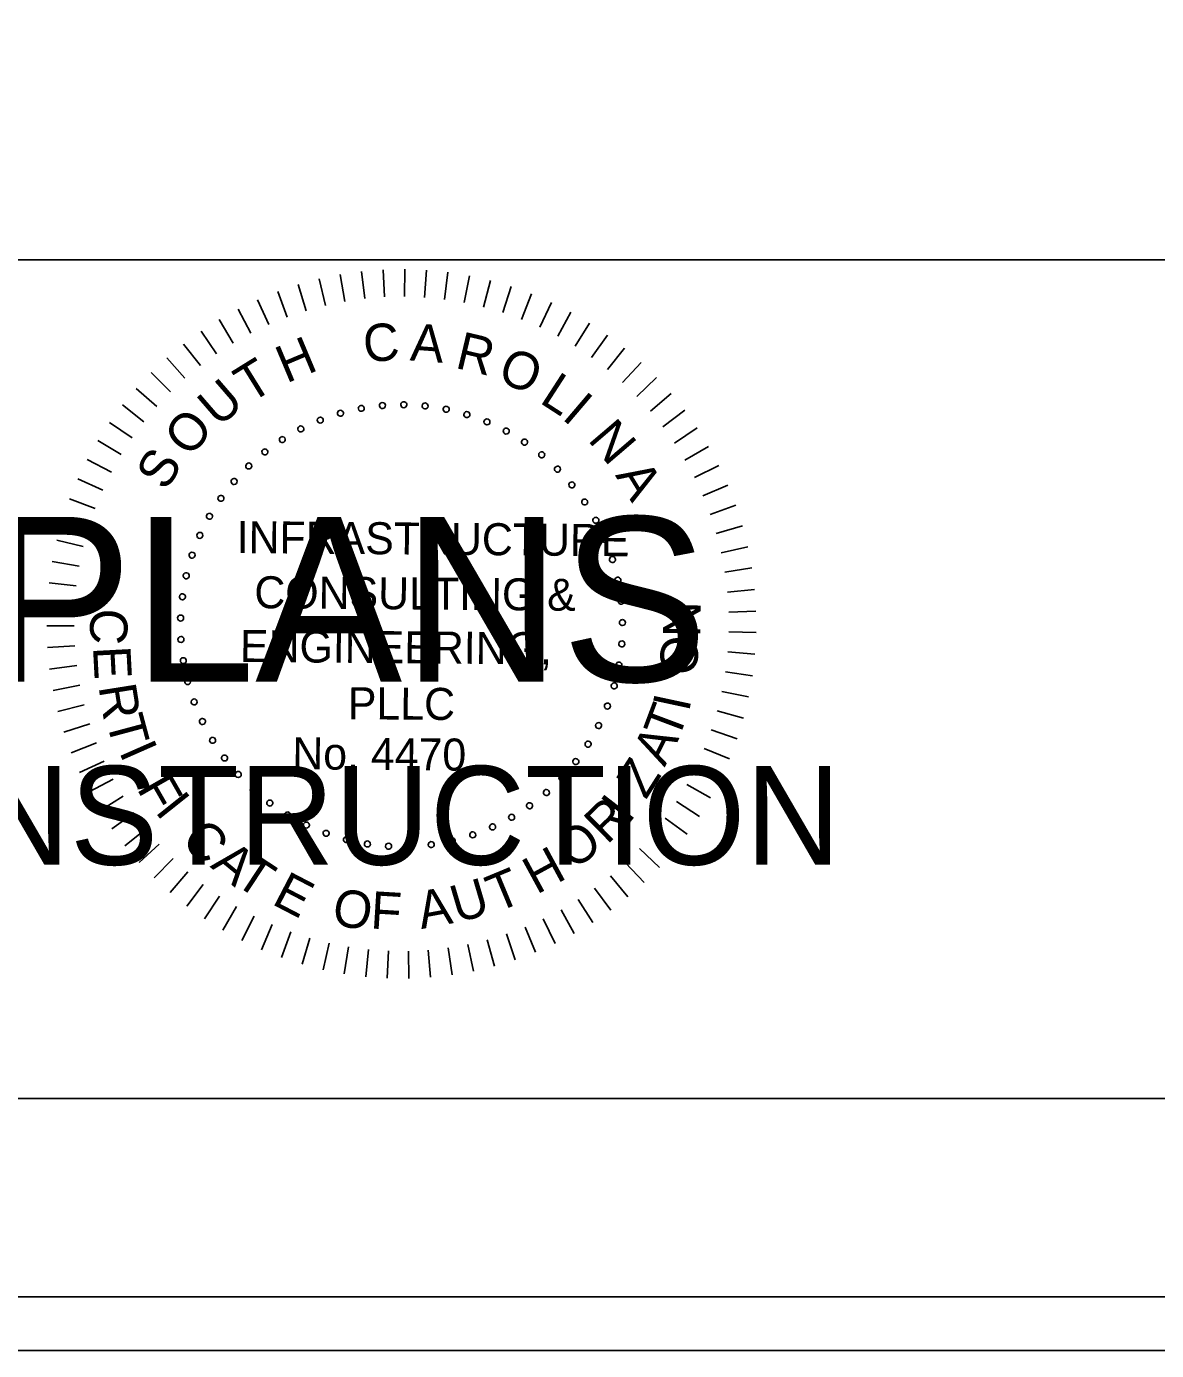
# Model space of a CAD drawing. Extents: x 967 to 1326, y 964 to 2864.
# Drawn here: x 1189.3 to 1212.88, y 2363.72 to 2391.36 of the extents above; entities that cross this region are included whole.
import ezdxf

# ---------------------------------------------------------------- set-up
doc = ezdxf.new("R2010")
doc.units = 0
for name, color, linetype in [('RD_PD_Final_TX', 7, 'Continuous'), ('RD_XS_TX_Elev_PR', 7, 'Continuous'), ('RD_XS_TX_Misc', 7, 'Continuous'), ('RD_XS_TX_ShdSlope', 7, 'Continuous')]:
    doc.layers.add(name, color=color, linetype=linetype)

msp = doc.modelspace()

# ---------------------------------------------------------------- linework, layer by layer
at = {"layer": 'RD_PD_Final_TX'}
for p, q in [((996.114, 2386.486), (1323.886, 2386.486)), ((1323.886, 2368.983), (996.114, 2368.983))]:
    msp.add_line(p, q, dxfattribs=at)
at = {"layer": 'RD_XS_TX_Elev_PR'}
for points in [[(967.409, 2363.72), (1326.285, 2363.72), (1326.285, 2583.72), (967.409, 2583.72)], [(988.525, 2364.84), (1326.285, 2364.84), (1326.285, 2582.6), (988.525, 2582.6)]]:
    msp.add_lwpolyline(points, close=True, dxfattribs=at)
at = {"layer": 'RD_XS_TX_ShdSlope'}
for p, q in [((1195.846, 2386.181), (1195.945, 2385.62)), ((1196.292, 2386.245), (1196.357, 2385.68)), ((1196.742, 2386.282), (1196.772, 2385.714)), ((1197.194, 2386.292), (1197.189, 2385.723)), ((1197.645, 2386.274), (1197.606, 2385.706)), ((1198.094, 2386.228), (1198.02, 2385.664)), ((1198.54, 2386.156), (1198.432, 2385.596)), ((1194.968, 2385.971), (1195.134, 2385.427)), ((1195.403, 2386.09), (1195.536, 2385.536)), ((1198.98, 2386.056), (1198.838, 2385.504)), ((1199.414, 2385.929), (1199.238, 2385.387)), ((1194.122, 2385.656), (1194.353, 2385.136)), ((1194.54, 2385.827), (1194.739, 2385.293)), ((1199.839, 2385.777), (1199.63, 2385.246)), ((1200.253, 2385.598), (1200.013, 2385.082)), ((1193.715, 2385.461), (1193.978, 2384.956)), ((1200.656, 2385.395), (1200.385, 2384.894)), ((1193.321, 2385.241), (1193.614, 2384.752)), ((1201.047, 2385.167), (1200.745, 2384.684)), ((1192.94, 2384.997), (1193.263, 2384.528)), ((1201.422, 2384.917), (1201.092, 2384.453)), ((1192.576, 2384.731), (1192.926, 2384.282)), ((1201.781, 2384.643), (1201.424, 2384.2)), ((1192.228, 2384.443), (1192.605, 2384.016)), ((1202.124, 2384.349), (1201.739, 2383.928)), ((1191.899, 2384.134), (1192.301, 2383.731)), ((1202.447, 2384.034), (1202.038, 2383.638)), ((1191.589, 2383.805), (1192.015, 2383.428)), ((1202.751, 2383.7), (1202.318, 2383.329)), ((1191.299, 2383.459), (1191.748, 2383.108)), ((1203.034, 2383.348), (1202.579, 2383.004)), ((1191.032, 2383.095), (1191.501, 2382.772)), ((1203.294, 2382.979), (1202.82, 2382.664)), ((1190.787, 2382.716), (1191.274, 2382.422)), ((1203.532, 2382.595), (1203.04, 2382.31)), ((1190.565, 2382.323), (1191.07, 2382.059)), ((1203.746, 2382.198), (1203.237, 2381.943)), ((1190.368, 2381.916), (1190.888, 2381.684)), ((1203.936, 2381.788), (1203.412, 2381.564)), ((1190.196, 2381.499), (1190.729, 2381.299)), ((1204.1, 2381.367), (1203.563, 2381.176)), ((1190.05, 2381.072), (1190.594, 2380.905)), ((1204.238, 2380.937), (1203.691, 2380.779)), ((1189.93, 2380.636), (1190.484, 2380.503)), ((1204.349, 2380.5), (1203.794, 2380.375)), ((1189.837, 2380.195), (1190.398, 2380.095)), ((1204.434, 2380.056), (1203.872, 2379.966)), ((1189.771, 2379.748), (1190.337, 2379.683)), ((1204.491, 2379.608), (1203.925, 2379.552)), ((1189.732, 2379.298), (1190.301, 2379.267)), ((1204.522, 2379.158), (1203.953, 2379.137)), ((1189.721, 2378.847), (1190.29, 2378.851)), ((1204.524, 2378.706), (1203.955, 2378.72)), ((1189.737, 2378.396), (1190.306, 2378.434)), ((1204.499, 2378.256), (1203.932, 2378.304)), ((1189.781, 2377.946), (1190.346, 2378.019)), ((1204.447, 2377.807), (1203.884, 2377.89)), ((1189.852, 2377.5), (1190.412, 2377.608)), ((1204.367, 2377.363), (1203.81, 2377.479)), ((1189.951, 2377.06), (1190.502, 2377.201)), ((1204.261, 2376.924), (1203.712, 2377.074)), ((1190.076, 2376.626), (1190.617, 2376.8)), ((1204.128, 2376.492), (1203.589, 2376.676)), ((1190.227, 2376.2), (1190.757, 2376.408)), ((1203.969, 2376.07), (1203.442, 2376.286)), ((1190.403, 2375.785), (1190.92, 2376.024)), ((1190.605, 2375.381), (1191.106, 2375.651)), ((1203.784, 2375.658), (1203.271, 2375.906)), ((1203.574, 2375.258), (1203.078, 2375.537)), ((1190.831, 2374.99), (1191.315, 2375.291)), ((1203.341, 2374.871), (1202.862, 2375.18)), ((1191.081, 2374.614), (1191.545, 2374.943)), ((1203.085, 2374.5), (1202.626, 2374.837)), ((1191.353, 2374.253), (1191.796, 2374.61)), ((1191.646, 2373.91), (1192.067, 2374.293)), ((1202.806, 2374.145), (1202.368, 2374.509)), ((1191.96, 2373.585), (1192.356, 2373.994)), ((1202.506, 2373.807), (1202.092, 2374.197)), ((1192.293, 2373.28), (1192.664, 2373.712)), ((1202.186, 2373.488), (1201.796, 2373.903)), ((1192.644, 2372.996), (1192.988, 2373.45)), ((1201.847, 2373.19), (1201.484, 2373.628)), ((1193.011, 2372.734), (1193.327, 2373.208)), ((1201.491, 2372.912), (1201.155, 2373.372)), ((1193.394, 2372.495), (1193.68, 2372.987)), ((1200.731, 2372.425), (1200.453, 2372.922)), ((1201.119, 2372.657), (1200.811, 2373.136)), ((1193.791, 2372.279), (1194.047, 2372.788)), ((1194.2, 2372.088), (1194.424, 2372.612)), ((1200.331, 2372.217), (1200.083, 2372.73)), ((1194.62, 2371.923), (1194.812, 2372.459)), ((1195.05, 2371.783), (1195.208, 2372.33)), ((1199.495, 2371.877), (1199.312, 2372.416)), ((1199.918, 2372.034), (1199.702, 2372.561)), ((1195.487, 2371.67), (1195.612, 2372.225)), ((1195.93, 2371.584), (1196.021, 2372.146)), ((1196.377, 2371.524), (1196.434, 2372.091)), ((1196.828, 2371.493), (1196.85, 2372.062)), ((1197.279, 2371.488), (1197.267, 2372.058)), ((1197.73, 2371.512), (1197.683, 2372.079)), ((1198.179, 2371.562), (1198.097, 2372.126)), ((1198.624, 2371.64), (1198.508, 2372.198)), ((1199.063, 2371.745), (1198.913, 2372.295))]:
    msp.add_line(p, q, dxfattribs=at)
for centre, start, end in [((1196.285, 2383.388), 10.6038, 190.6038), ((1196.285, 2383.388), 190.6038, 10.6038), ((1196.727, 2383.447), 5.0653, 185.0653), ((1196.727, 2383.447), 185.0653, 5.0653), ((1197.172, 2383.464), 359.5268, 179.5268), ((1197.172, 2383.464), 179.5268, 359.5268), ((1197.617, 2383.438), 173.9884, 353.9884), ((1197.617, 2383.438), 353.9884, 173.9884), ((1198.057, 2383.369), 168.4499, 348.4499), ((1198.057, 2383.369), 348.4499, 168.4499), ((1195.429, 2383.142), 21.6807, 201.6807), ((1195.429, 2383.142), 201.6807, 21.6807), ((1195.851, 2383.285), 16.1422, 196.1422), ((1195.851, 2383.285), 196.1422, 16.1422), ((1198.489, 2383.258), 162.9114, 342.9114), ((1198.489, 2383.258), 342.9114, 162.9114), ((1198.908, 2383.106), 157.373, 337.373), ((1198.908, 2383.106), 337.373, 157.373), ((1195.023, 2382.958), 27.2191, 207.2191), ((1195.023, 2382.958), 207.2191, 27.2191), ((1199.31, 2382.914), 151.8345, 331.8345), ((1199.31, 2382.914), 331.8345, 151.8345), ((1194.637, 2382.736), 32.7576, 212.7576), ((1194.637, 2382.736), 212.7576, 32.7576), ((1199.692, 2382.684), 146.2961, 326.2961), ((1199.692, 2382.684), 326.2961, 146.2961), ((1194.274, 2382.478), 38.2961, 218.2961), ((1194.274, 2382.478), 218.2961, 38.2961), ((1200.05, 2382.419), 140.7576, 320.7576), ((1200.05, 2382.419), 320.7576, 140.7576), ((1193.937, 2382.186), 43.8345, 223.8345), ((1193.937, 2382.186), 223.8345, 43.8345), ((1200.38, 2382.12), 135.2191, 315.2191), ((1200.38, 2382.12), 315.2191, 135.2191), ((1193.63, 2381.862), 49.373, 229.373), ((1193.63, 2381.862), 229.373, 49.373), ((1200.68, 2381.79), 129.6807, 309.6807), ((1200.68, 2381.79), 309.6807, 129.6807), ((1193.356, 2381.511), 54.9114, 234.9114), ((1193.356, 2381.511), 234.9114, 54.9114), ((1200.947, 2381.433), 124.1422, 304.1422), ((1200.947, 2381.433), 304.1422, 124.1422), ((1193.117, 2381.135), 60.4499, 240.4499), ((1193.117, 2381.135), 240.4499, 60.4499), ((1201.179, 2381.052), 118.6038, 298.6038), ((1201.179, 2381.052), 298.6038, 118.6038), ((1192.915, 2380.737), 65.9884, 245.9884), ((1192.915, 2380.737), 245.9884, 65.9884), ((1201.372, 2380.651), 113.0653, 293.0653), ((1201.372, 2380.651), 293.0653, 113.0653), ((1192.753, 2380.322), 71.5268, 251.5268), ((1192.753, 2380.322), 251.5268, 71.5268), ((1201.526, 2380.233), 107.5268, 287.5268), ((1201.526, 2380.233), 287.5268, 107.5268), ((1192.632, 2379.894), 77.0653, 257.0653), ((1192.632, 2379.894), 257.0653, 77.0653), ((1201.638, 2379.801), 101.9884, 281.9884), ((1201.638, 2379.801), 281.9884, 101.9884), ((1192.552, 2379.455), 82.6038, 262.6038), ((1192.552, 2379.455), 262.6038, 82.6038), ((1201.709, 2379.361), 96.4499, 276.4499), ((1201.709, 2379.361), 276.4499, 96.4499), ((1192.515, 2379.011), 88.1422, 268.1422), ((1192.515, 2379.011), 268.1422, 88.1422), ((1201.737, 2378.917), 90.9114, 270.9114), ((1201.737, 2378.917), 270.9114, 90.9114), ((1192.522, 2378.565), 93.6807, 273.6807), ((1192.522, 2378.565), 273.6807, 93.6807), ((1201.721, 2378.471), 85.373, 265.373), ((1201.721, 2378.471), 265.373, 85.373), ((1192.571, 2378.122), 99.2191, 279.2191), ((1192.571, 2378.122), 279.2191, 99.2191), ((1201.663, 2378.029), 79.8345, 259.8345), ((1201.663, 2378.029), 259.8345, 79.8345), ((1192.662, 2377.686), 104.7576, 284.7576), ((1192.662, 2377.686), 284.7576, 104.7576), ((1201.563, 2377.595), 74.2961, 254.2961), ((1201.563, 2377.595), 254.2961, 74.2961), ((1192.796, 2377.261), 110.2961, 290.2961), ((1192.796, 2377.261), 290.2961, 110.2961), ((1201.42, 2377.173), 68.7576, 248.7576), ((1201.42, 2377.173), 248.7576, 68.7576), ((1192.97, 2376.851), 115.8345, 295.8345), ((1192.97, 2376.851), 295.8345, 115.8345), ((1201.238, 2376.766), 63.2191, 243.2191), ((1201.238, 2376.766), 243.2191, 63.2191), ((1193.182, 2376.459), 121.373, 301.373), ((1193.182, 2376.459), 301.373, 121.373), ((1201.018, 2376.379), 57.6807, 237.6807), ((1201.018, 2376.379), 237.6807, 57.6807), ((1193.432, 2376.09), 126.9114, 306.9114), ((1193.432, 2376.09), 306.9114, 126.9114), ((1200.761, 2376.014), 52.1422, 232.1422), ((1200.761, 2376.014), 232.1422, 52.1422), ((1193.715, 2375.746), 132.4499, 312.4499), ((1193.715, 2375.746), 312.4499, 132.4499), ((1200.47, 2375.677), 46.6038, 226.6038), ((1200.47, 2375.677), 226.6038, 46.6038), ((1194.031, 2375.431), 137.9884, 317.9884), ((1194.031, 2375.431), 317.9884, 137.9884), ((1200.148, 2375.369), 41.0653, 221.0653), ((1200.148, 2375.369), 221.0653, 41.0653), ((1194.376, 2375.149), 143.5268, 323.5268), ((1194.376, 2375.149), 323.5268, 143.5268), ((1199.798, 2375.093), 35.5268, 215.5268), ((1199.798, 2375.093), 215.5268, 35.5268), ((1194.746, 2374.901), 149.0653, 329.0653), ((1194.746, 2374.901), 329.0653, 149.0653), ((1199.422, 2374.853), 29.9884, 209.9884), ((1199.422, 2374.853), 209.9884, 29.9884), ((1195.139, 2374.69), 154.6038, 334.6038), ((1195.139, 2374.69), 334.6038, 154.6038), ((1195.55, 2374.517), 160.1422, 340.1422), ((1195.55, 2374.517), 340.1422, 160.1422), ((1198.611, 2374.486), 18.9114, 198.9114), ((1199.026, 2374.65), 24.4499, 204.4499), ((1199.026, 2374.65), 204.4499, 24.4499), ((1195.975, 2374.386), 165.6807, 345.6807), ((1195.975, 2374.386), 345.6807, 165.6807), ((1196.412, 2374.295), 171.2191, 351.2191), ((1196.412, 2374.295), 351.2191, 171.2191), ((1196.855, 2374.248), 356.7576, 176.7576), ((1197.301, 2374.243), 2.2961, 182.2961), ((1197.745, 2374.282), 7.8345, 187.8345), ((1197.745, 2374.282), 187.8345, 7.8345), ((1198.183, 2374.363), 13.373, 193.373), ((1198.183, 2374.363), 193.373, 13.373), ((1198.611, 2374.486), 198.9114, 18.9114), ((1196.855, 2374.248), 176.7576, 356.7576), ((1197.301, 2374.243), 182.2961, 2.2961)]:
    msp.add_arc(centre, 0.0627, start, end, dxfattribs=at)

# ---------------------------------------------------------------- texts
at = {"layer": 'RD_XS_TX_Misc'}
for s, height, p in [('FINAL PLANS', 3.4375, (1174.145, 2377.685)), ('NOT FOR CONSTRUCTION', 2.0625, (1170.901, 2373.86))]:
    msp.add_text(s, height=height, dxfattribs=at).set_placement(p)
at = {"layer": 'RD_XS_TX_ShdSlope'}
for s, height, rotation, p in [('C', 0.78, 4.7281, (1196.355, 2384.346)), ('A', 0.78, 355.6981, (1197.29, 2384.39)), ('H', 0.78, 22.7882, (1194.72, 2383.904)), ('R', 0.78, 346.6681, (1198.222, 2384.238)), ('O', 0.78, 337.638, (1199.096, 2383.972)), ('T', 0.78, 31.8182, (1193.961, 2383.478)), ('U', 0.78, 40.8482, (1193.306, 2382.976)), ('L', 0.78, 327.108, (1199.981, 2383.52)), ('I', 0.78, 319.578, (1200.451, 2383.182)), ('O', 0.78, 49.8782, (1192.707, 2382.341)), ('N', 0.78, 310.548, (1200.994, 2382.728)), ('S', 0.78, 58.9083, (1192.211, 2381.642)), ('A', 0.78, 301.5179, (1201.576, 2381.991)), ('INFRASTRUCTURE', 0.66873, 359.5268, (1193.682, 2380.367)), ('CONSULTING &', 0.66873, 359.5268, (1194.051, 2379.217)), ('N', 0.78, 89.2085, (1203.359, 2378.604)), ('C', 0.78, 267.025, (1190.646, 2379.227)), ('ENGINEERING,', 0.66873, 359.5268, (1193.751, 2378.095)), ('O', 0.78, 83.2085, (1203.26, 2377.786)), ('E', 0.78, 273.025, (1190.685, 2378.408)), ('R', 0.78, 279.025, (1190.799, 2377.583)), ('PLLC', 0.6687, 359.5268, (1196.002, 2376.9)), ('I', 0.78, 77.9093, (1203.121, 2377.032)), ('T', 0.78, 285.025, (1190.955, 2376.878)), ('T', 0.78, 69.3954, (1202.891, 2376.428)), ('No. 4470', 0.6687, 359.5268, (1194.843, 2375.855)), ('A', 0.78, 63.3954, (1202.616, 2375.888)), ('I', 0.78, 293.7713, (1191.221, 2376.225)), ('Z', 0.78, 57.3954, (1202.224, 2375.206)), ('F', 0.78, 299.7713, (1191.589, 2375.455)), ('I', 0.78, 308.5268, (1191.965, 2374.973)), ('R', 0.78, 44.5268, (1201.415, 2374.267)), ('I', 0.78, 52.3339, (1201.856, 2374.69)), ('C', 0.78, 314.5268, (1192.496, 2374.346)), ('O', 0.78, 38.5268, (1200.73, 2373.731)), ('A', 0.78, 320.5268, (1193.115, 2373.822)), ('T', 0.78, 326.5268, (1193.602, 2373.478)), ('H', 0.78, 28.5268, (1199.942, 2373.23)), ('E', 0.78, 332.5268, (1194.394, 2373.051)), ('T', 0.78, 22.5268, (1199.108, 2372.856)), ('U', 0.78, 16.5268, (1198.288, 2372.638)), ('O', 0.78, 350.5268, (1195.647, 2372.614)), ('F', 0.78, 356.5268, (1196.465, 2372.532)), ('A', 0.78, 10.5268, (1197.537, 2372.517))]:
    msp.add_text(s, height=height, rotation=rotation, dxfattribs=at).set_placement(p)

doc.saveas('drawing.dxf')
